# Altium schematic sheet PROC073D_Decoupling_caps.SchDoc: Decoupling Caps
size 431 x 279 mm; Date: Not shown in title block; ApprovedBy: Not shown in title block; CheckedBy: Not shown in title block; Author: Not shown in title block; CompanyName: Not shown in title block; DrawnBy: Charles F. Oladimeji; Engineer: Not shown in title block; Organization: Not shown in title block; Address1: Not shown in title block; Address2: Not shown in title block; Address3: Not shown in title block; Address4: Not shown in title block; DocumentNumber: 5; Revision: Use project parameter SCH_Rev; SheetNumber: 5; SheetTotal: 13; PageSetup: Record=PageOptions¦CenterHorizontal=True¦CenterVertical=True¦PrintScale=1.00¦XCorrection=1.00¦YCorrection=1.00¦PrintKind=0¦BorderSize=5000000¦LeftOffset=0¦BottomOffset=0¦Orientation=2¦PaperLength=1000¦PaperWidth=1000¦Scale=100¦PaperSource=15¦PrintQuality=600¦MediaType=1¦DitherType=10¦PaperKind=Letter¦PrintScaleMode=1
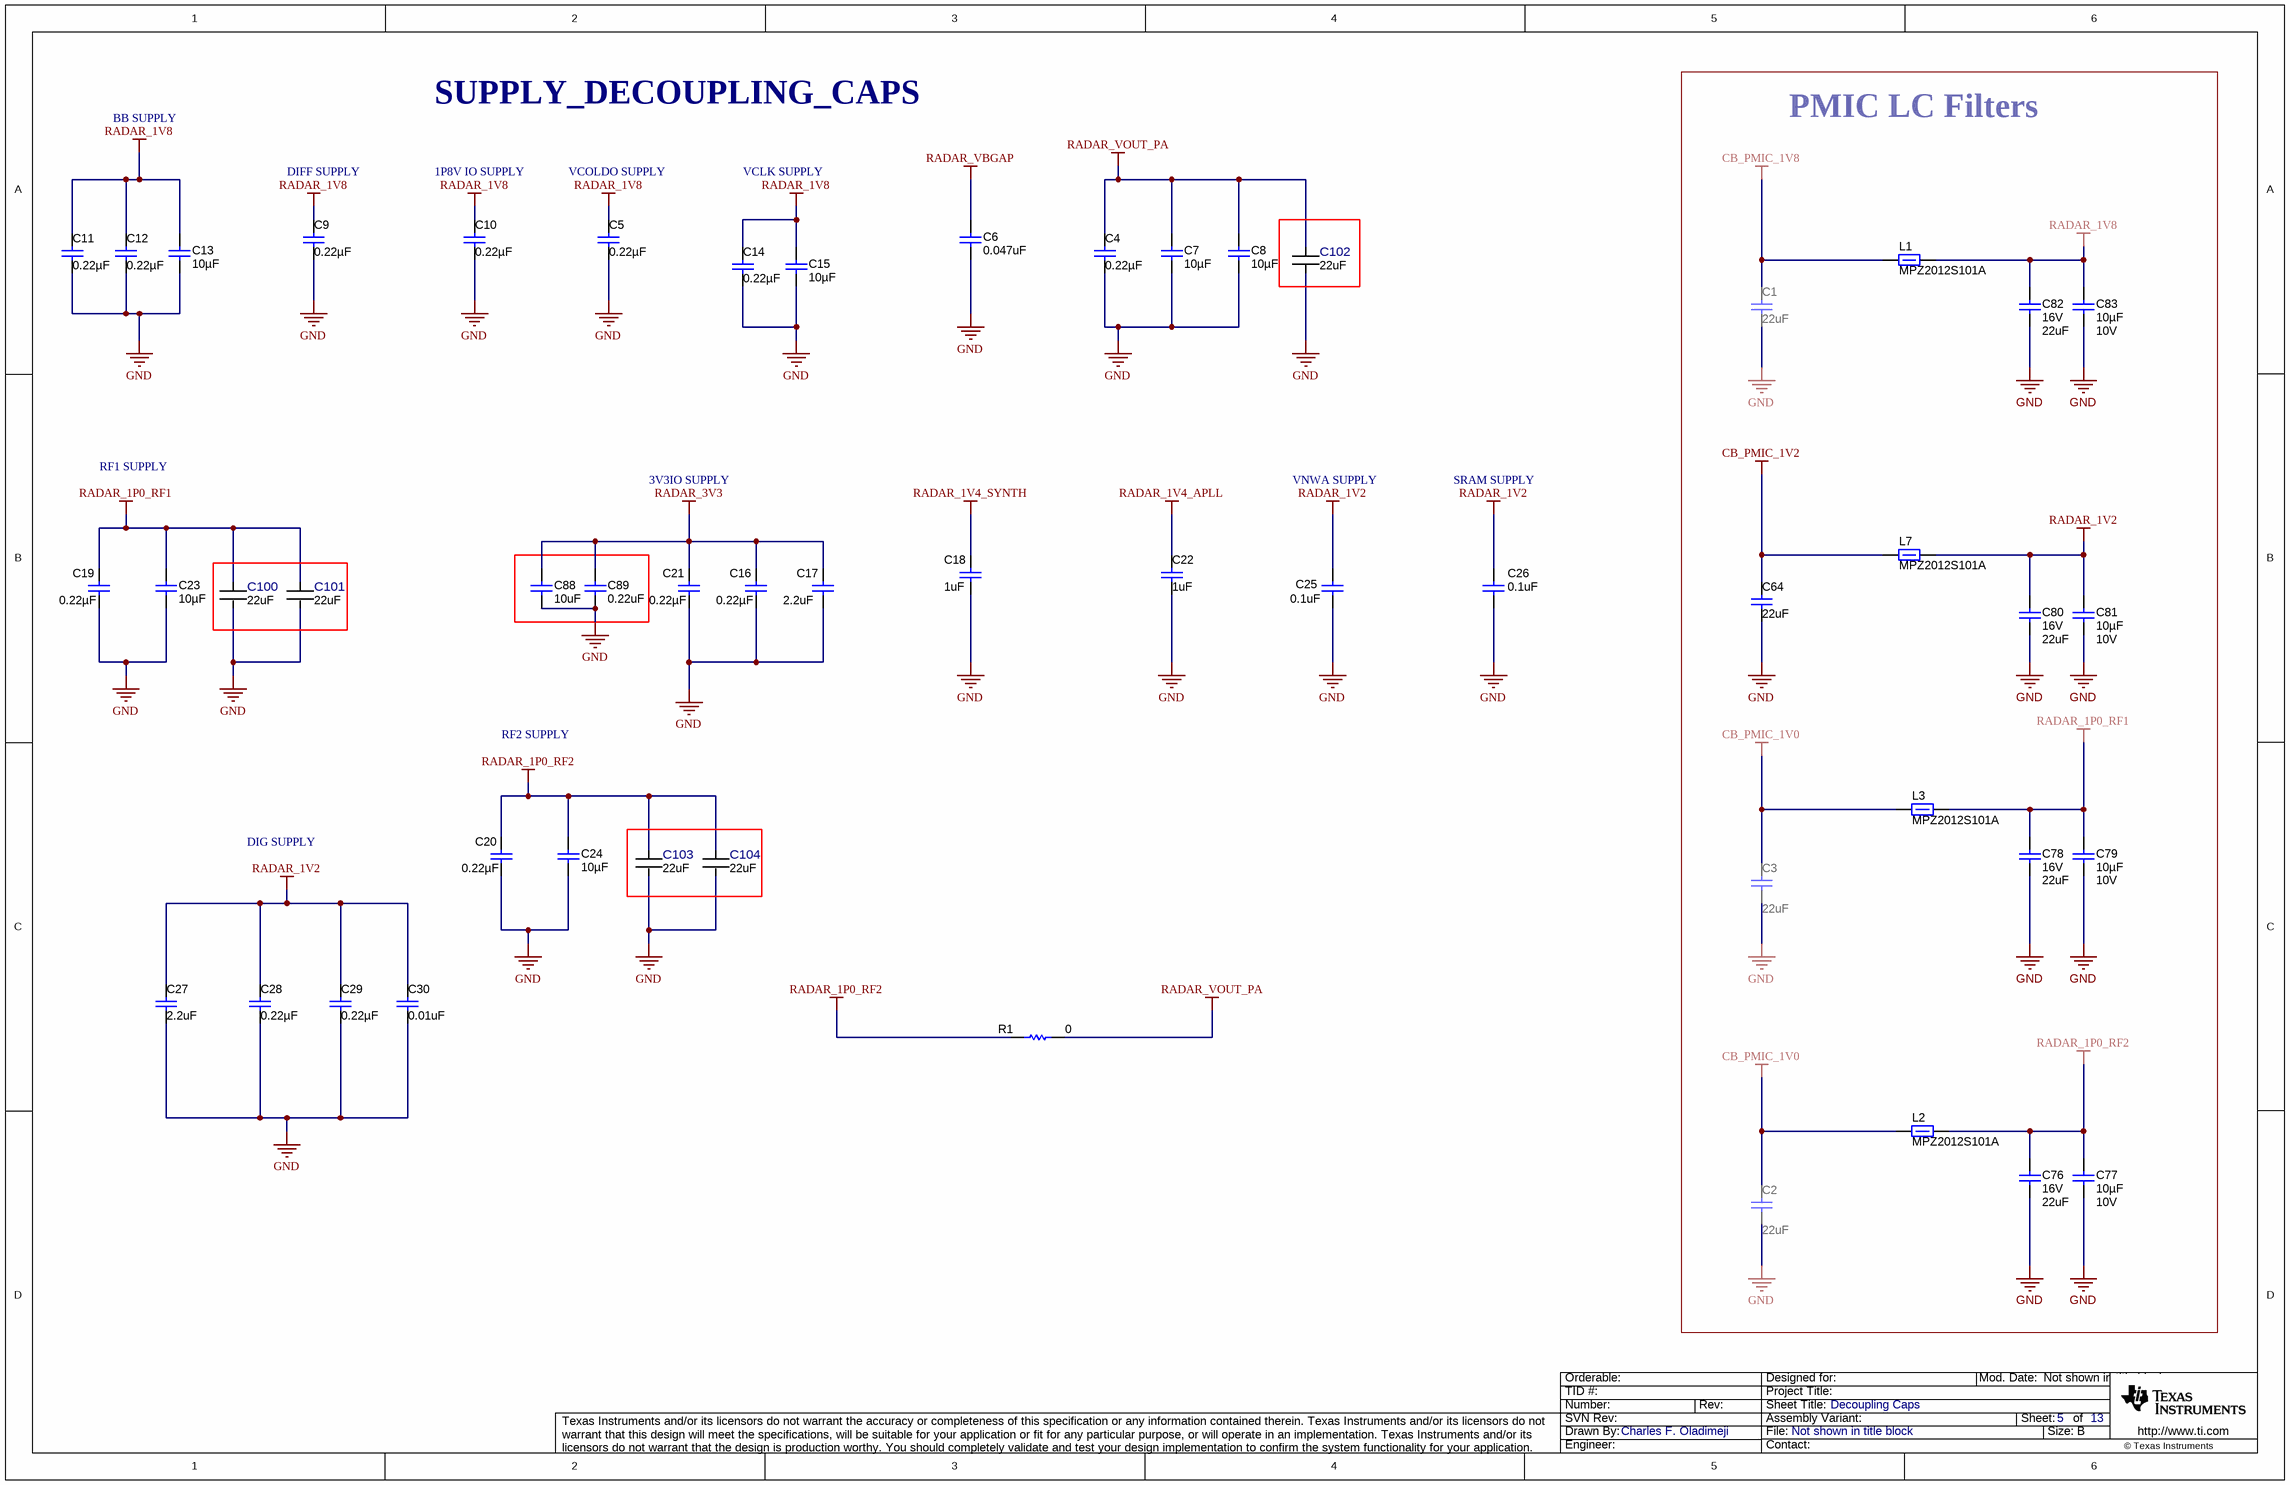
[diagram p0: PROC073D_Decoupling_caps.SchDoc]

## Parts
C1  ValueDisplayed: 22uF  [1206_180]  (hidden comment: CGA5L1X7R0J226M160AC)
C2  ValueDisplayed: 22uF  [1206_180]  (hidden comment: CGA5L1X7R0J226M160AC)
C3  ValueDisplayed: 22uF  [1206_180]  (hidden comment: CGA5L1X7R0J226M160AC)
C4  ValueDisplayed: 0.22µF  [0402L]  (hidden comment: GCM155R71C224KE02D)
C5  ValueDisplayed: 0.22µF  [0402L]  (hidden comment: GCM155R71C224KE02D)
C6  ValueDisplayed: 0.047uF  [0402L]  (hidden comment: CGA2B3X7R1H473K050BB)
C7  Cap_F: 10µF  [0805_HV]  (hidden comment: C0805C106M8RACTU)
C8  Cap_F: 10µF  [0805_HV]  (hidden comment: C0805C106M8RACTU)
C9  ValueDisplayed: 0.22µF  [0402L]  (hidden comment: GCM155R71C224KE02D)
C10  ValueDisplayed: 0.22µF  [0402L]  (hidden comment: GCM155R71C224KE02D)
C11  ValueDisplayed: 0.22µF  [0402L]  (hidden comment: GCM155R71C224KE02D)
C12  ValueDisplayed: 0.22µF  [0402L]  (hidden comment: GCM155R71C224KE02D)
C13  Cap_F: 10µF  [0805_HV]  (hidden comment: C0805C106M8RACTU)
C14  ValueDisplayed: 0.22µF  [0402L]  (hidden comment: GCM155R71C224KE02D)
C15  Cap_F: 10µF  [0805_HV]  (hidden comment: C0805C106M8RACTU)
C16  ValueDisplayed: 0.22µF  [0402L]  (hidden comment: GCM155R71C224KE02D)
C17  ValueDisplayed: 2.2uF  [0603]  (hidden comment: GCM188R70J225KE22D)
C18  ValueDisplayed: 1uF  [0603]  (hidden comment: GCM188R71C105KA64D)
C19  ValueDisplayed: 0.22µF  [0402L]  (hidden comment: GCM155R71C224KE02D)
C20  ValueDisplayed: 0.22µF  [0402L]  (hidden comment: GCM155R71C224KE02D)
C21  ValueDisplayed: 0.22µF  [0402L]  (hidden comment: GCM155R71C224KE02D)
C22  ValueDisplayed: 1uF  [0603]  (hidden comment: GCM188R71C105KA64D)
C23  Cap_F: 10µF  [0805_HV]  (hidden comment: C0805C106M8RACTU)
C24  Cap_F: 10µF  [0805_HV]  (hidden comment: C0805C106M8RACTU)
C25  ValueDisplayed: 0.1uF  [0402L]  (hidden comment: GCM155R71C104KA55D)
C26  ValueDisplayed: 0.1uF  [0402L]  (hidden comment: GCM155R71C104KA55D)
C27  ValueDisplayed: 2.2uF  [0603]  (hidden comment: GCM188R70J225KE22D)
C28  ValueDisplayed: 0.22µF  [0402L]  (hidden comment: GCM155R71C224KE02D)
C29  ValueDisplayed: 0.22µF  [0402L]  (hidden comment: GCM155R71C224KE02D)
C30  ValueDisplayed: 0.01uF  [0402L]  (hidden comment: GCM155R71E103KA37D)
C64  ValueDisplayed: 22uF  [1206_180]  (hidden comment: CGA5L1X7R0J226M160AC)
C76  VDC_V: 16V  ValueDisplayed: 22uF  [1210_280]  (hidden comment: GCM32ER71C226KE19L)
C77  Cap_F: 10µF  VDC_V: 10V  [0805_HV]  (hidden comment: GCM21BR71A106KE22L)
C78  VDC_V: 16V  ValueDisplayed: 22uF  [1210_280]  (hidden comment: GCM32ER71C226KE19L)
C79  Cap_F: 10µF  VDC_V: 10V  [0805_HV]  (hidden comment: GCM21BR71A106KE22L)
C80  VDC_V: 16V  ValueDisplayed: 22uF  [1210_280]  (hidden comment: GCM32ER71C226KE19L)
C81  Cap_F: 10µF  VDC_V: 10V  [0805_HV]  (hidden comment: GCM21BR71A106KE22L)
C82  VDC_V: 16V  ValueDisplayed: 22uF  [1210_280]  (hidden comment: GCM32ER71C226KE19L)
C83  Cap_F: 10µF  VDC_V: 10V  [0805_HV]  (hidden comment: GCM21BR71A106KE22L)
C88  ValueDisplayed: 10uF  [0603S]  (hidden comment: GRT188R61A106KE13D)
C89  ValueDisplayed: 0.22uF  [0402S]  (hidden comment: LMK105B7224KVHF)
C100  Cap_F: 22uF  [FP-CL05A226MQ5N6J8_0402 (1005 Metric)-IPC_C]  (hidden comment: CL05A226MQ5N6J8)
C101  Cap_F: 22uF  [FP-CL05A226MQ5N6J8_0402 (1005 Metric)-IPC_C]  (hidden comment: CL05A226MQ5N6J8)
C102  Cap_F: 22uF  [FP-CL05A226MQ5N6J8_0402 (1005 Metric)-IPC_C]  (hidden comment: CL05A226MQ5N6J8)
C103  Cap_F: 22uF  [FP-CL05A226MQ5N6J8_0402 (1005 Metric)-IPC_C]  (hidden comment: CL05A226MQ5N6J8)
C104  Cap_F: 22uF  [FP-CL05A226MQ5N6J8_0402 (1005 Metric)-IPC_C]  (hidden comment: CL05A226MQ5N6J8)
L1  MPZ2012S101A  [MPZ2012]
L2  MPZ2012S101A  [MPZ2012]
L3  MPZ2012S101A  [MPZ2012]
L7  MPZ2012S101A  [MPZ2012]
R1  ValueDisplayed: 0  [0603]  (hidden comment: MCT06030Z0000ZP500)

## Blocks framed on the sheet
PMIC LC Filters: C1-C3 C64 C76-C83 L1-L3 L7

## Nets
CB_PMIC_1V0: C2.2 C3.2 L2.1 L3.1
CB_PMIC_1V2: C64.2 L7.1
CB_PMIC_1V8: C1.2 L1.1
GND: C1.1 C2.1 C3.1 C4.1 C5.1 C6.2 C7.1 C8.1 C9.1 C10.1 C11.1 C12.1 C13.1 C14.1 C15.1 C16.1 C17.1 C18.1 C19.1 C20.1 C21.1 C22.1 C23.1 C24.1 C25.1 C26.1 C27.1 C28.1 C29.1 C30.2 C64.1 C76.2 C77.2 C78.2 C79.2 C80.2 C81.2 C82.2 C83.2 C88.1 C89.2 C100.2 C101.2 C102.2 C103.2 C104.2
RADAR_1P0_RF1: C19.2 C23.2 C78.1 C79.1 C100.1 C101.1 L3.2
RADAR_1P0_RF2: C20.2 C24.2 C76.1 C77.1 C103.1 C104.1 L2.2 R1.1
RADAR_1V2: C25.2 C26.2 C27.2 C28.2 C29.2 C30.1 C80.1 C81.1 L7.2
RADAR_1V4_APLL: C22.2
RADAR_1V4_SYNTH: C18.2
RADAR_1V8: C5.2 C9.2 C10.2 C11.2 C12.2 C13.2 C14.2 C15.2 C82.1 C83.1 L1.2
RADAR_3V3: C16.2 C17.2 C21.2 C88.2 C89.1
RADAR_VBGAP: C6.1
RADAR_VOUT_PA: C4.2 C7.2 C8.2 C102.1 R1.2

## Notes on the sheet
- BB SUPPLY
- SUPPLY_DECOUPLING_CAPS
- DIFF SUPPLY
- 1P8V IO SUPPLY
- VCOLDO SUPPLY
- VCLK SUPPLY
- RF1 SUPPLY
- 3V3IO SUPPLY
- VNWA SUPPLY
- SRAM SUPPLY
- RF2 SUPPLY
- DIG SUPPLY

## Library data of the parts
C1-C3 C64 = CMP-0008770-2: CAP, CERM, 22 uF, 6.3 V, +/- 10%, X7R, AEC-Q200 Grade 1, 1206; Manufacturer: TDK; TaMin_C: -55°C; ESR_ohm: 1.872m; Polarized: N; SizeAreaWB_mm2: 10.92; Value1: 0.001872 ohm; U/M: EA; Value: 22uF; SizeZ_mm: 1.8; SizeX_mm: 3.2; SizeY_mm: 1.6; Value2: 6.3V; SizeArea_mm2: 5.12; CompType: Capacitor; AEC Qualified: Y; Cap_F: 22µF; IRMS_A: 5.30203A; AEC Grade: 1; AEC Category: Q200; TaMax_C: 125°C; INSTALLATION: DNP
C4 C5 C9-C12 C14 C16 C19-C21 C28 C29 = CMP-0078265-1: CAP, CERM, 0.22 µF, 16 V,+/- 10%, X7R, AEC-Q200 Grade 1, 0402; Manufacturer: MuRata; TaMin_C: -55°C; Polarized: N; SizeAreaWB_mm2: 3; U/M: EA; Value: 0.22uF; TaMax_C: 125°C; SizeZ_mm: 0.6; SizeX_mm: 1; SizeY_mm: 0.5; Cap_Case: 0402; Value2: 16V; CompType: Capacitor; AEC Qualified: Y; Cap_F: 220nF; AEC Category: Q200
C6 = CMP-0006330-2: CAP, CERM, 0.047 uF, 50 V, +/- 10%, X7R, AEC-Q200 Grade 1, 0402; Manufacturer: TDK; Polarized: N; U/M: EA; Cap_F: 47nF; ESR_ohm: 0.06407; Value1: 0.06407 ohm; VDC_V: 50V; IRMS_A: 646.122mA; TaMin_C: -55°C; TaMax_C: 125°C; Cap_Case: 0402; SizeArea_mm2: 0.5; SizeAreaWB_mm2: 3; SizeX_mm: 1; SizeZ_mm: 0.6; AEC Category: Q200; AEC Qualified: Y
C7 C8 C13 C15 C23 C24 = CMP-0085348-1: CAP, CERM, 10 µF, 10 V,+/- 20%, X7R, 0805; Manufacturer: Kemet; TaMin_C: -55°C; SizeZ_mm: 1.45; U/M: EA; SizeY_mm: 1.25; Value2: 10V; SizeAreaWB_mm2: 6.75; SizeArea_mm2: 2.5; Value: 10uF; AEC Qualified: N; TaMax_C: 125°C; SizeX_mm: 2; Cap_Case: 0805; AEC Category: Q200
C17 C27 = CMP-0007134-5: CAP, CERM, 2.2 uF, 6.3 V, +/- 10%, X7R, AEC-Q200 Grade 1, 0603; Manufacturer: MuRata; TaMin_C: -55°C; Polarized: N; SizeAreaWB_mm2: 4.68; Value1: Unknown; U/M: EA; Value: 2.2uF; TaMax_C: 125°C; SizeZ_mm: 1; SizeX_mm: 1.6; SizeY_mm: 0.8; Value2: 6.3V; SizeArea_mm2: 1.28; CompType: Capacitor; AEC Qualified: Y; Cap_F: 2.2µF; AEC Category: Q200
C18 C22 = CMP-0007136-5: CAP, CERM, 1 uF, 16 V, +/- 10%, X7R, AEC-Q200 Grade 1, 0603; Manufacturer: MuRata; TaMin_C: -55°C; Polarized: N; SizeAreaWB_mm2: 4.68; Value1: Unknown; U/M: EA; Value: 1uF; TaMax_C: 125°C; SizeZ_mm: 1; SizeX_mm: 1.6; SizeY_mm: 0.8; Value2: 16V; SizeArea_mm2: 1.28; CompType: Capacitor; AEC Qualified: Y; Cap_F: 1µF; AEC Category: Q200
C25 C26 = CMP-0006351-2: CAP, CERM, 0.1 uF, 16 V, +/- 10%, X7R, 0402; Manufacturer: MuRata; TaMin_C: -55°C; Polarized: N; SizeAreaWB_mm2: 3; Value1: Unknown; U/M: EA; Value: 0.1uF; TaMax_C: 125°C; SizeZ_mm: 0.6; SizeX_mm: 1; SizeY_mm: 0.5; Cap_Case: 0402; Value2: 16V; CompType: Capacitor; Cap_F: 100nF; AEC Category: Q200
C30 = CMP-0006352-2: CAP, CERM, 0.01 uF, 25 V, +/- 10%, X7R, 0402; Manufacturer: MuRata; TaMin_C: -55°C; Polarized: N; SizeAreaWB_mm2: 3; Value1: Unknown; U/M: EA; Value: 0.01uF; TaMax_C: 125°C; SizeZ_mm: 0.6; SizeX_mm: 1; SizeY_mm: 0.5; Cap_Case: 0402; Value2: 25V; CompType: Capacitor; Cap_F: 10nF; AEC Category: Q200
C76 C78 C80 C82 = CMP-0009174-2: CAP, CERM, 22 uF, 16 V, +/- 10%, X7R, 1210; Manufacturer: MuRata; TaMin_C: -55°C; Polarized: N; SizeAreaWB_mm2: 14.7; Value1: Unknown; U/M: EA; Value: 22uF; TaMax_C: 125°C; SizeZ_mm: 2.8; SizeX_mm: 3.2; SizeY_mm: 2.5; Cap_Case: 1210; SizeArea_mm2: 8; Cap_F: 22µF; AEC Category: Q200
C77 C79 C81 C83 = CMP-0008017-2: CAP, CERM, 10 uF, 10 V, +/- 10%, X7R, 0805; Manufacturer: MuRata; TaMin_C: -55°C; Polarized: N; SizeAreaWB_mm2: 6.75; Value1: Unknown; U/M: EA; Value: 10uF; TaMax_C: 125°C; SizeZ_mm: 1.45; SizeX_mm: 2; SizeY_mm: 1.25; Cap_Case: 0805; SizeArea_mm2: 2.5; AEC Category: Q200
C88 = CMP-0007497-5: CAP, CERM, 10 uF, 10 V, +/- 10%, X5R, 0603; Manufacturer: MuRata; Polarized: N; Value: 10uF; U/M: EA; Cap_F: 10µF; Tolerance_%: 20%; Value1: Unknown; VDC_V: 10V; TempCo: X7R; TaMin_C: -55°C; TaMax_C: 125°C; Cap_Case: 0603; SizeArea_mm2: 1.28; SizeAreaWB_mm2: 4.68; SizeX_mm: 1.6; SizeY_mm: 0.8; SizeZ_mm: 1; AEC Category: Q200
C89 = CMP-0006262-2: CAP, CERM, 0.22 uF, 10 V, +/- 10%, X7R, 0402; Manufacturer: TDK; Polarized: N; Value: 0.22uF; U/M: EA; Cap_F: 220nF; Value1: Unknown; VDC_V: 10V; TempCo: X5R; TaMin_C: -55°C; TaMax_C: 85°C; Cap_Case: 0402; SizeArea_mm2: 0.5; SizeAreaWB_mm2: 3; SizeX_mm: 1; SizeZ_mm: 0.6; AEC Category: Q200
C100-C104 = CMP-0086447-1: CAP CER 22UF 6.3V X5R 0402; Manufacturer: Samsung Electro-Mechanics; AEC Qualified: No; SizeZ_mm: 0.55mm; Symbol Name: SYM-CL05A226MQ5N6J8; TempCo: 15%; Tolerance_%: 20%
L1-L3 L7 = CMP-0003427-2: Ferrite Bead, 100 ohm @ 100 MHz, 4 A, 0805; Manufacturer: TDK; Value1: 0.02 ohm; Value: 100 ohm; Imax_A: 4A; DCR_ohm: 0.02; ZTyp@100MHz_Ohm: 100
R1 = CMP-0025884-3: RES, 0, 5%, 0.125 W, 0603; Manufacturer: Vishay/Beyschlag; Power_W: 125mW; TempCo: ppm/C; Value_Code: 0000; U/M: EA; Value: 0; EIA_Code: E24; SizeX_mm: 1.6; SizeY_mm: 0.8; SizeZ_mm: 1; Value2: 0.125W; SizeArea_mm2: 1.28; CompType: Resistor; AEC Qualified: N; AEC Category: Q200; INSTALATION: DNP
